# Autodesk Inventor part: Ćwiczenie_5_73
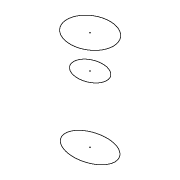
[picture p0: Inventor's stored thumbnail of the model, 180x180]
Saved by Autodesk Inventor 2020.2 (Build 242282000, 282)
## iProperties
Created: 2005-08
Part Number: Ćwiczenie_5_73
Document SubType Name: Modeling
Designer: F.Stasiak
Manufacturer: Standard
Standards Organization: Custom
Density: 1 g/cm^3
Material: Ogólny
Appearance: Domyślna
Manager: www.cadconsulting.pl
Company: Fabian Stasiak CAD Consulting
Author: F.Stasiak
Subject: Zbiór ćwiczeń. Autodesk Inventor 2020. Kurs podstawowy
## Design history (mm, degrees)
sketch "Szkic1"
  geometry: 2 further points; 1 other entity
  constraints: 1 coincident, 2 other
node "Płaszczyzna konstrukcyjna1"
sketch "Szkic2"
  geometry: 2 further points; 1 other entity
  constraints: 1 coincident, 2 other
node "Płaszczyzna konstrukcyjna2"
sketch "Szkic3"
  geometry: 2 further points; 1 other entity
  constraints: 1 coincident, 2 other
node "Korpusy bryłowe"
node "Korpusy powierzchniowe"
